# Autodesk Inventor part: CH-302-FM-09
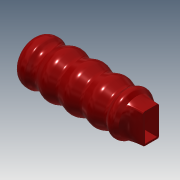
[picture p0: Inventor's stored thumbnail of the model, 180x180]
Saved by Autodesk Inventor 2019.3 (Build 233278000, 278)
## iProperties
Created: 2012-09
Part Number: CH-302-FM-09
Material: Ogólny
Document SubType Name: Modeling
Designer: CADENGINEERING4
Density: 1 g/cm^3
Appearance: Czerwona
Author: CADENGINEERING4
Revision Number: ÈÎºÎ
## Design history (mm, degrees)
feature "Ô²½Ç11"
node "Bryła1"
